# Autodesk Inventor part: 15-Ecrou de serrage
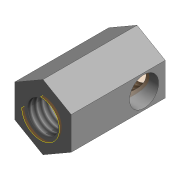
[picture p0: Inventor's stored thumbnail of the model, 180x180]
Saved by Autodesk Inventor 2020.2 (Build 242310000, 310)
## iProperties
Created: 2022-03
Part Number: 15-Ecrou de serrage
Material: Générique
Document SubType Name: Modeling
Designer: %USERNAME%
Density: 1 g/cm^3
Appearance: Par défaut
Author: %USERNAME%
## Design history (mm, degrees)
sketch "Esquisse2"
  geometry: L1 (6, 3.464)-(6, -3.464); L2 (6, -3.464)-(0, -6.928); L3 (0, -6.928)-(-6, -3.464); L4 (-6, -3.464)-(-6, 3.464); L5 (-6, 3.464)-(0, 6.928); L6 (0, 6.928)-(6, 3.464); 2 further points
  constraints: 12 end point, 1 coincident, 1 vertical, 13 other
  dimensions: "d0" = 12 distance between parallel lines of L2 L5
extrude "Extrusion1" new body sketch "Esquisse2" distance "d1" = 20; taper "d2" = 0 deg
sketch "Esquisse3"
  geometry: 2 further points
hole "Perçage1" sketch "Esquisse3" at (0, 0) diameter "d3" = 6.647; stored, may be unused: countersink angle "d7" = 90 deg, drill point angle "d9" = 118 deg; dims "d4" = 16, "d5" = 4, "d6" = 2, "d8" = 22.2
sketch "Esquisse4"
  geometry: L1 (0, 0)-(0, 6.928) reference; 3 further points
  constraints: 1 horizontal alignment, 1 midpoint
  dimensions: "d10" = 4.5 distance of point (0, 3.464) point (-4.5, 3.464)
hole "Perçage2" sketch "Esquisse4" at (-4.5, 3.464) diameter "d11" = 6.2; stored, may be unused: countersink angle "d15" = 90 deg, drill point angle "d17" = 118 deg; dims "d12" = 16, "d13" = 4, "d14" = 2, "d16" = 22.2
sketch "Esquisse5"
  geometry: C1 r 3.324 at (0, 0) reference; A1 r 4 centre (0, 0) between (0, 4) and (4, 0); 1 further point
  constraints: 2 point on circle, 1 centre point, 1 coincident
  dimensions: "d18" = 4 radius of A1
feature "SrfExtrusion1" sketch "Esquisse5" dims "d19" = 0.5, "d20" = 20.5, "d21" = 0, "d22" = 0
node "Solide1"
body "Srf1"
